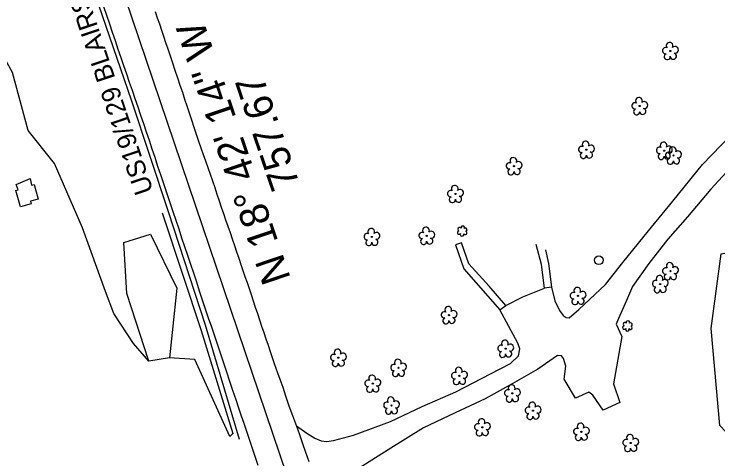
# Model space of a CAD drawing. Extents: x 478596 to 483012, y 490885 to 495165.
# Drawn here: x 481144.5 to 481532.8, y 491989.7 to 492235.2 of the extents above; entities that cross this region are included whole.
import ezdxf

# ---------------------------------------------------------------- set-up
doc = ezdxf.new("R2010")
doc.units = 0
for name, color, linetype in [('Exist Guardrail', 7, 'Continuous'), ('Exist Horizontal Alignment', 7, 'Continuous'), ('Exist Horizontal Alignment Direction Label', 7, 'Continuous'), ('Exist Other Culture Area Outline', 7, 'Continuous'), ('Exist Roads EOP', 7, 'Continuous'), ('Exist Roads EOP Text', 7, 'Continuous'), ('Exist Roads Soil', 7, 'Continuous'), ('Exist Utilities Other Pole CELL', 7, 'Continuous'), ('Exist Vegetation Hedge Row', 7, 'Continuous'), ('Exist Vegetation Shrub CELL', 7, 'Continuous'), ('Exist Vegetation Tree CELL', 7, 'Continuous'), ('Exist Vegetation Woods Line', 7, 'Continuous')]:
    doc.layers.add(name, color=color, linetype=linetype)

msp = doc.modelspace()

# ---------------------------------------------------------------- linework, layer by layer
at = {"layer": 'Exist Guardrail'}
msp.add_lwpolyline([(481268.81, 492000.43), (481250.05, 492063.45), (481229.61, 492126.12), (481209.51, 492187.09), (481191.12, 492240.55), (481159.92, 492332.85)], dxfattribs=at)
at = {"layer": 'Exist Horizontal Alignment'}
msp.add_line((481314.86, 491922.25), (481071.89, 492639.91), dxfattribs=at)
at = {"layer": 'Exist Other Culture Area Outline'}
for points in [[(481153.29, 492144.42), (481154.14, 492140.68), (481155.63, 492141.04), (481157.7, 492133.06), (481153.45, 492131.84), (481153.94, 492130.47), (481147.95, 492128.76), (481145.4, 492137.87), (481146.77, 492138.11), (481145.67, 492141.11), (481153.29, 492144.42)], [(481415.76, 492074.38), (481406.52, 492084.97), (481395.29, 492097.26), (481391.38, 492109.02), (481387.93, 492107.83), (481392.56, 492094.68), (481412.42, 492071.99), (481415.76, 492074.38)], [(481435.47, 492097.02), (481432.57, 492108.07)], [(481437.64, 492105), (481439.4, 492097.48)], [(481437.07, 492083.89), (481435.47, 492097.02)], [(481439.4, 492097.48), (481440.94, 492084.41), (481437.07, 492083.89)]]:
    msp.add_lwpolyline(points, dxfattribs=at)
at = {"layer": 'Exist Roads EOP'}
for points in [[(481279.22, 491986.13), (481277.93, 491989.98), (481276.64, 491993.83), (481275.34, 491997.69), (481274.02, 492001.56), (481272.7, 492005.44), (481271.37, 492009.32), (481269.98, 492013.37), (481268.5, 492017.73), (481266.91, 492022.39), (481265.22, 492027.37), (481263.5, 492032.48), (481261.8, 492037.55), (481260.12, 492042.57), (481258.46, 492047.56), (481256.81, 492052.52), (481255.15, 492057.49), (481253.49, 492062.46), (481251.82, 492067.43), (481250.15, 492072.4), (481248.5, 492077.36), (481246.85, 492082.31), (481245.22, 492087.25), (481243.59, 492092.16), (481241.97, 492097.06), (481240.34, 492101.92), (481238.71, 492106.77), (481237.08, 492111.6), (481235.46, 492116.43), (481233.83, 492121.26), (481232.21, 492126.1), (481230.58, 492130.97), (481228.93, 492135.91), (481227.25, 492140.91), (481225.55, 492145.98), (481223.86, 492151.02), (481222.23, 492155.93), (481220.63, 492160.71), (481219.09, 492165.36), (481217.56, 492169.96), (481216.02, 492174.55), (481214.45, 492179.15), (481212.87, 492183.75), (481211.29, 492188.34), (481209.72, 492192.91), (481208.17, 492197.46), (481206.62, 492202), (481205.08, 492206.54), (481203.53, 492211.1), (481201.98, 492215.7), (481200.41, 492220.33), (481198.84, 492224.98), (481197.26, 492229.67), (481195.66, 492234.39), (481194.06, 492239.14)], [(481222.35, 492236.54), (481223.49, 492233.16), (481224.64, 492229.74), (481225.79, 492226.31), (481226.94, 492222.88), (481228.09, 492219.43), (481229.28, 492215.9), (481230.53, 492212.17), (481231.85, 492208.26), (481233.24, 492204.17), (481234.64, 492200.03), (481236, 492196), (481237.3, 492192.07), (481238.57, 492188.25), (481239.81, 492184.45), (481241.08, 492180.61), (481242.38, 492176.73), (481243.69, 492172.79), (481245, 492168.89), (481246.3, 492165.07), (481247.58, 492161.35), (481248.85, 492157.73), (481250.1, 492154.13), (481251.37, 492150.5), (481252.64, 492146.83), (481253.91, 492143.13), (481255.18, 492139.43), (481256.41, 492135.79), (481257.62, 492132.2), (481258.8, 492128.66), (481259.98, 492125.15), (481261.17, 492121.64), (481262.38, 492118.11), (481263.6, 492114.59), (481264.82, 492111.06), (481266.02, 492107.54), (481267.22, 492104.02), (481268.4, 492100.5), (481269.57, 492097.03), (481270.73, 492093.61), (481271.86, 492090.27), (481272.98, 492086.99), (481274.1, 492083.71), (481275.23, 492080.36), (481276.38, 492076.95), (481277.54, 492073.47), (481278.71, 492069.95), (481279.88, 492066.44), (481281.06, 492062.93), (481282.23, 492059.42), (481283.4, 492055.93), (481284.56, 492052.47), (481285.72, 492049.03), (481286.87, 492045.63), (481287.96, 492042.44), (481289.77, 492037.29), (481291.11, 492033.69), (481292.68, 492029.21), (481294.19, 492024.58), (481296.04, 492019.09), (481298.02, 492013.74), (481299.79, 492009.19), (481300.85, 492006.29), (481302.15, 492002.59), (481303.64, 491998.29), (481305.3, 491993.45), (481307, 491988.34)]]:
    msp.add_lwpolyline(points, dxfattribs=at)
at = {"layer": 'Exist Roads Soil'}
for points in [[(481440.94, 492084.41), (481442.81, 492076.92), (481445.44, 492071.59), (481447.48, 492068.85), (481448.98, 492067.81), (481450.79, 492067.5), (481456.14, 492072.12), (481470.81, 492085.87), (481480.33, 492098.08), (481494.47, 492115.53), (481507.95, 492132.01), (481524.29, 492152.16), (481539.75, 492168.2), (481553.39, 492182.26), (481553.4, 492182.27)], [(481541.64, 492152.28), (481528.97, 492138.64), (481515.93, 492123.37), (481505.14, 492110.98), (481494.65, 492097.5), (481485.68, 492084.92), (481482.42, 492077.15), (481477.88, 492067.14), (481476.71, 492064.12), (481479.81, 492057.21), (481475.16, 492031.05), (481478.6, 492020.75), (481469.5, 492016.7), (481463.87, 492024.96), (481461.53, 492026.49), (481454.31, 492023.21), (481448.03, 492033.71), (481448.92, 492040.9), (481447.62, 492045.14), (481446.42, 492046.54), (481444.3, 492046.74), (481433.43, 492039.19), (481419.35, 492031.06), (481404.41, 492022.87), (481387.79, 492015.12), (481370.38, 492006.77), (481350.89, 491994.81), (481334.92, 491984.69)], [(481415.76, 492074.38), (481425.11, 492079.22), (481437.07, 492083.89)], [(481300.24, 492007.9), (481305.9, 492003.94), (481310.36, 492001.12), (481313.85, 491999.71), (481316.93, 491999.27), (481320.69, 491999.85), (481331.71, 492002.86), (481352.2, 492010.34), (481369.68, 492018.69), (481388.23, 492026.73), (481407.41, 492036.64), (481418.39, 492042.31), (481422.78, 492046.64), (481423.47, 492050.45), (481422.46, 492053.66), (481412.42, 492071.99)]]:
    msp.add_lwpolyline(points, dxfattribs=at)
at = {"layer": 'Exist Utilities Other Pole CELL'}
msp.add_circle((481467.1, 492099.36), 2.46, dxfattribs=at)
at = {"layer": 'Exist Vegetation Hedge Row'}
for points in [[(481218.82, 492043.64), (481210.36, 492053.43), (481199.59, 492070.01), (481194.83, 492082.01), (481182.3, 492117.17), (481166.69, 492152.71), (481152.18, 492170.83), (481143.63, 492202.94), (481118.35, 492248.52), (481084.64, 492335.71)], [(481226.17, 492125.55), (481226.94, 492123.21), (481247.75, 492060.54), (481265.18, 492003.69), (481263.56, 492001.99), (481244.2, 492044.6), (481230.17, 492045.55)]]:
    msp.add_lwpolyline(points, dxfattribs=at)
at = {"layer": 'Exist Vegetation Shrub CELL'}
for p, q in [((481391.77, 492115.3), (481391.77, 492115.3)), ((481482.96, 492062.95), (481482.96, 492062.95))]:
    msp.add_line(p, q, dxfattribs=at)
for centre, radius, start, end in [((481389.97, 492114.59), 0.955, 95.1099, 327.9534), ((481390.29, 492116.42), 0.968, 35.8908, 245.4216), ((481392, 492117.34), 0.99, 334.8391, 200.4717), ((481393.41, 492114.37), 0.937, 204.9913, 73.4601), ((481393.44, 492116.16), 0.929, 284.4567, 126.0861), ((481391.64, 492113.61), 0.984, 151.2797, 21.387), ((481481.48, 492064.07), 0.968, 35.8908, 245.4216), ((481483.19, 492064.99), 0.99, 334.8391, 200.4717), ((481484.63, 492063.82), 0.929, 284.4567, 126.0861), ((481481.16, 492062.24), 0.955, 95.1099, 327.9534), ((481482.83, 492061.26), 0.984, 151.2797, 21.387), ((481484.6, 492062.02), 0.937, 204.9913, 73.4601)]:
    msp.add_arc(centre, radius, start, end, dxfattribs=at)
at = {"layer": 'Exist Vegetation Tree CELL'}
for p, q in [((481506.54, 492214.8), (481506.54, 492214.8)), ((481489.65, 492184.4), (481489.65, 492184.4)), ((481460.23, 492160.32), (481460.23, 492160.32)), ((481503.18, 492159.78), (481503.18, 492159.78)), ((481508.27, 492157.14), (481508.27, 492157.14)), ((481420.32, 492151.25), (481420.32, 492151.25)), ((481387.97, 492135.9), (481387.97, 492135.9)), ((481341.86, 492112.17), (481341.86, 492112.17)), ((481372.13, 492112.84), (481372.13, 492112.84)), ((481506.62, 492093.28), (481506.62, 492093.28)), ((481500.95, 492086.21), (481500.95, 492086.21)), ((481455.58, 492079.66), (481455.58, 492079.66)), ((481384.41, 492069.05), (481384.41, 492069.05)), ((481415.67, 492050.54), (481415.67, 492050.54)), ((481323.37, 492045.55), (481323.37, 492045.55)), ((481356.57, 492039.98), (481356.57, 492039.98)), ((481390.17, 492035.52), (481390.17, 492035.52)), ((481342.38, 492031.25), (481342.38, 492031.25)), ((481419.39, 492025.9), (481419.39, 492025.9)), ((481352.7, 492019.21), (481352.7, 492019.21)), ((481430.76, 492016.32), (481430.76, 492016.32)), ((481402.8, 492007.17), (481402.8, 492007.17)), ((481457.45, 492004.69), (481457.45, 492004.69)), ((481484.68, 491998.53), (481484.68, 491998.53))]:
    msp.add_line(p, q, dxfattribs=at)
for centre in [(481506.54, 492214.8), (481489.65, 492184.4), (481460.23, 492160.32), (481503.18, 492159.78), (481508.27, 492157.14), (481420.32, 492151.25), (481387.97, 492135.9), (481341.86, 492112.17), (481372.13, 492112.84), (481506.62, 492093.28), (481500.95, 492086.21), (481455.58, 492079.66), (481384.41, 492069.05), (481415.67, 492050.54), (481323.37, 492045.55), (481356.57, 492039.98), (481390.17, 492035.52), (481342.38, 492031.25), (481419.39, 492025.9), (481352.7, 492019.21), (481430.76, 492016.32), (481402.8, 492007.17), (481457.45, 492004.69), (481484.68, 491998.53)]:
    msp.add_circle(centre, 0.326, dxfattribs=at)
for centre, radius, start, end in [((481503.93, 492214.95), 1.73, 62.6636, 279.3457), ((481506.15, 492217.67), 1.86, 330.1651, 219.7134), ((481509.09, 492215.39), 1.9, 257.1011, 134.1999), ((481504.83, 492211.68), 1.69, 111.5671, 6.231), ((481508.21, 492211.9), 1.7, 181.2822, 74.56), ((481489.26, 492187.28), 1.86, 330.1651, 219.7134), ((481487.04, 492184.56), 1.73, 62.6636, 279.3457), ((481492.2, 492184.99), 1.9, 257.1011, 134.1999), ((481487.95, 492181.28), 1.69, 111.5671, 6.231), ((481491.32, 492181.5), 1.7, 181.2822, 74.56), ((481457.62, 492160.47), 1.73, 62.6636, 279.3457), ((481459.84, 492163.19), 1.86, 330.1651, 219.7134), ((481462.78, 492160.91), 1.9, 257.1011, 134.1999), ((481500.58, 492159.94), 1.73, 62.6636, 279.3457), ((481502.8, 492162.66), 1.86, 330.1651, 219.7134), ((481505.73, 492160.37), 1.9, 257.1011, 134.1999), ((481507.89, 492160.01), 1.86, 330.1651, 219.7134), ((481458.52, 492157.2), 1.69, 111.5671, 6.231), ((481461.9, 492157.42), 1.7, 181.2822, 74.56), ((481501.48, 492156.66), 1.69, 111.5671, 6.231), ((481504.86, 492156.88), 1.7, 181.2822, 74.56), ((481505.66, 492157.29), 1.73, 62.6636, 279.3457), ((481510.82, 492157.72), 1.9, 257.1011, 134.1999), ((481419.94, 492154.12), 1.86, 330.1651, 219.7134), ((481422.87, 492151.83), 1.9, 257.1011, 134.1999), ((481506.57, 492154.01), 1.69, 111.5671, 6.231), ((481509.94, 492154.24), 1.7, 181.2822, 74.56), ((481417.72, 492151.4), 1.73, 62.6636, 279.3457), ((481421.99, 492148.35), 1.7, 181.2822, 74.56), ((481418.62, 492148.12), 1.69, 111.5671, 6.231), ((481387.58, 492138.77), 1.86, 330.1651, 219.7134), ((481390.52, 492136.48), 1.9, 257.1011, 134.1999), ((481385.36, 492136.05), 1.73, 62.6636, 279.3457), ((481386.26, 492132.77), 1.69, 111.5671, 6.231), ((481389.64, 492133), 1.7, 181.2822, 74.56), ((481341.48, 492115.04), 1.86, 330.1651, 219.7134), ((481371.74, 492115.71), 1.86, 330.1651, 219.7134), ((481374.67, 492113.43), 1.9, 257.1011, 134.1999), ((481339.26, 492112.32), 1.73, 62.6636, 279.3457), ((481344.41, 492112.76), 1.9, 257.1011, 134.1999), ((481369.52, 492112.99), 1.73, 62.6636, 279.3457), ((481370.42, 492109.72), 1.69, 111.5671, 6.231), ((481373.8, 492109.94), 1.7, 181.2822, 74.56), ((481340.16, 492109.05), 1.69, 111.5671, 6.231), ((481343.54, 492109.27), 1.7, 181.2822, 74.56), ((481506.23, 492096.16), 1.86, 330.1651, 219.7134), ((481509.17, 492093.87), 1.9, 257.1011, 134.1999), ((481504.01, 492093.44), 1.73, 62.6636, 279.3457), ((481504.91, 492090.16), 1.69, 111.5671, 6.231), ((481508.29, 492090.38), 1.7, 181.2822, 74.56), ((481498.34, 492086.36), 1.73, 62.6636, 279.3457), ((481500.57, 492089.08), 1.86, 330.1651, 219.7134), ((481503.5, 492086.8), 1.9, 257.1011, 134.1999), ((481455.2, 492082.53), 1.86, 330.1651, 219.7134), ((481499.25, 492083.09), 1.69, 111.5671, 6.231), ((481502.62, 492083.31), 1.7, 181.2822, 74.56), ((481452.98, 492079.82), 1.73, 62.6636, 279.3457), ((481458.13, 492080.25), 1.9, 257.1011, 134.1999), ((481453.88, 492076.54), 1.69, 111.5671, 6.231), ((481457.25, 492076.76), 1.7, 181.2822, 74.56), ((481384.03, 492071.93), 1.86, 330.1651, 219.7134), ((481381.81, 492069.21), 1.73, 62.6636, 279.3457), ((481386.96, 492069.64), 1.9, 257.1011, 134.1999), ((481382.71, 492065.93), 1.69, 111.5671, 6.231), ((481386.08, 492066.15), 1.7, 181.2822, 74.56), ((481415.28, 492053.41), 1.86, 330.1651, 219.7134), ((481418.22, 492051.13), 1.9, 257.1011, 134.1999), ((481322.98, 492048.42), 1.86, 330.1651, 219.7134), ((481413.06, 492050.69), 1.73, 62.6636, 279.3457), ((481413.96, 492047.42), 1.69, 111.5671, 6.231), ((481417.34, 492047.64), 1.7, 181.2822, 74.56), ((481320.76, 492045.7), 1.73, 62.6636, 279.3457), ((481325.91, 492046.14), 1.9, 257.1011, 134.1999), ((481321.66, 492042.43), 1.69, 111.5671, 6.231), ((481325.04, 492042.65), 1.7, 181.2822, 74.56), ((481353.97, 492040.13), 1.73, 62.6636, 279.3457), ((481356.19, 492042.85), 1.86, 330.1651, 219.7134), ((481359.12, 492040.56), 1.9, 257.1011, 134.1999), ((481354.87, 492036.85), 1.69, 111.5671, 6.231), ((481358.25, 492037.08), 1.7, 181.2822, 74.56), ((481387.56, 492035.67), 1.73, 62.6636, 279.3457), ((481389.78, 492038.39), 1.86, 330.1651, 219.7134), ((481392.71, 492036.11), 1.9, 257.1011, 134.1999), ((481341.99, 492034.12), 1.86, 330.1651, 219.7134), ((481344.93, 492031.83), 1.9, 257.1011, 134.1999), ((481388.46, 492032.4), 1.69, 111.5671, 6.231), ((481391.84, 492032.62), 1.7, 181.2822, 74.56), ((481339.77, 492031.4), 1.73, 62.6636, 279.3457), ((481340.67, 492028.12), 1.69, 111.5671, 6.231), ((481344.05, 492028.35), 1.7, 181.2822, 74.56), ((481419, 492028.77), 1.86, 330.1651, 219.7134), ((481416.78, 492026.05), 1.73, 62.6636, 279.3457), ((481421.94, 492026.48), 1.9, 257.1011, 134.1999), ((481352.32, 492022.08), 1.86, 330.1651, 219.7134), ((481355.25, 492019.8), 1.9, 257.1011, 134.1999), ((481417.68, 492022.77), 1.69, 111.5671, 6.231), ((481421.06, 492023), 1.7, 181.2822, 74.56), ((481350.1, 492019.36), 1.73, 62.6636, 279.3457), ((481354.37, 492016.31), 1.7, 181.2822, 74.56), ((481428.15, 492016.48), 1.73, 62.6636, 279.3457), ((481430.37, 492019.2), 1.86, 330.1651, 219.7134), ((481433.3, 492016.91), 1.9, 257.1011, 134.1999), ((481351, 492016.09), 1.69, 111.5671, 6.231), ((481429.05, 492013.2), 1.69, 111.5671, 6.231), ((481432.43, 492013.42), 1.7, 181.2822, 74.56), ((481402.42, 492010.04), 1.86, 330.1651, 219.7134), ((481400.2, 492007.32), 1.73, 62.6636, 279.3457), ((481405.35, 492007.76), 1.9, 257.1011, 134.1999), ((481454.84, 492004.84), 1.73, 62.6636, 279.3457), ((481457.06, 492007.56), 1.86, 330.1651, 219.7134), ((481460, 492005.28), 1.9, 257.1011, 134.1999), ((481401.1, 492004.05), 1.69, 111.5671, 6.231), ((481404.48, 492004.27), 1.7, 181.2822, 74.56), ((481455.75, 492001.57), 1.69, 111.5671, 6.231), ((481459.12, 492001.79), 1.7, 181.2822, 74.56), ((481484.29, 492001.4), 1.86, 330.1651, 219.7134), ((481482.07, 491998.68), 1.73, 62.6636, 279.3457), ((481487.23, 491999.12), 1.9, 257.1011, 134.1999), ((481482.97, 491995.41), 1.69, 111.5671, 6.231), ((481486.35, 491995.63), 1.7, 181.2822, 74.56)]:
    msp.add_arc(centre, radius, start, end, dxfattribs=at)
at = {"layer": 'Exist Vegetation Woods Line'}
for points in [[(481219.66, 492113.73), (481234.28, 492084), (481230.17, 492045.55), (481218.82, 492043.64), (481206.62, 492081.07), (481205.06, 492109.1), (481219.66, 492113.73)], [(481370.78, 491853.85), (481351.95, 491906.77), (481366.45, 491914.77), (481410.8, 491899.16), (481421.42, 491903.82), (481409.89, 491948.85), (481428.87, 491957.06), (481440.61, 491925.36), (481455.59, 491930.86), (481468.91, 491949.08), (481502.11, 491961.68), (481520.4, 491958.45), (481540.45, 491959.56), (481547.5, 491970.59), (481550.62, 491990.5), (481533.93, 492008.17), (481529.05, 492061.74), (481534.56, 492102.92), (481577.42, 492110.74)]]:
    msp.add_lwpolyline(points, dxfattribs=at)

# ---------------------------------------------------------------- texts
at = {"layer": 'Exist Horizontal Alignment Direction Label'}
for s, p in [('N 18%%d 42\' 14" W', (481297.22, 492089.36)), ('757.67', (481302.2, 492141.16))]:
    msp.add_text(s, height=16, rotation=108.704, dxfattribs=at).set_placement(p)
at = {"layer": 'Exist Roads EOP Text'}
msp.add_text('US19/129 BLAIRSVILLE HWY', height=10.4, rotation=108.631, dxfattribs=at).set_placement((481221.44, 492137.55))

doc.saveas('drawing.dxf')
